(* Logix 5000 project; controller PDPMV1_60_v15 vendor 1 type 14 code 65 rev 15.1; software revision 15.00 *)
// MVI69-PDPMV1 sample ladder logic.

TASK MainTask (continuous, watchdog 500 ms) : MainProgram

MODULES
   Controller : vendor 1 type 14 code 65 (CompactLogixL35Controller 0, rev 15.1)
      LocalENB : 1769-L35E Ethernet Port (CompactLogixL35Ethernet 1, rev 15.1)
      Local : CompactBus (CompactVirtualAdapter 3, rev 15.1, Output RPI 2 ms)
         PDPMV1_60 : 1769-MODULE (Compact 1, rev 1.1, Output RPI 2 ms)   // MVI69-PDPMV1
END_MODULES

TYPE PDPMV1_AbortConnection :
STRUCT
   Out : PDPMV1_AbortConnection_out;   // Mailbox Request
   In : PDPMV1_AbortConnection_In;   // Mailbox Response
END_STRUCT
END_TYPE

TYPE PDPMV1_AbortConnection_In :
STRUCT
   C_REF : INT;   // Connection reference that shall be terminated.
   ReasonCode : SINT;   // Indicates the reason for the abort request. Value is user-specific. Range 0...15
   Subnet : SINT;   // This parameter encodes information about the origin of the abort initiator. 0: No 1: Local 2: Remote 3...255: (reserved)
   ExtendedFaultInformation : INT;   // If ‘Fault Information’ equals 000Ah or 000Bh, additional information of the error can be found
   FaultInformation : INT;   // If ‘Invalid Other’ is returned in the Message Information word in the header of the response,
END_STRUCT
END_TYPE

TYPE PDPMV1_AbortConnection_out :
STRUCT
   C_REF : INT;   // Connection reference that shall be terminated
   ReasonCode : SINT;   // Indicates the reason for the abort request. Value is user-specific. Range 0...15.
   Subnet : SINT;   // This parameter encodes information about the origin of the abort initiator. 0: No 1: Local 2: Remote
END_STRUCT
END_TYPE

TYPE PDPMV1_Alarm :   // DPV1 alarm data received by the module
STRUCT
   ByteCount : INT;   // Byte count data block
   SlotNumber : SINT;   // Used in the slave to address the desired data block. Range 0-254
   SlaveAddress : SINT;   // Destination of slave (1-125)
   AlarmSpecAck : SINT;   // Additional alarm information
   SeqNumber : SINT;   // Unique ID number of the alarm. Range 0-31.
   ExtDiag : SINT;   // Extended Diagnostic Flag (FFh - flag set and 00h - flag cleared).
   AlarmType : SINT;   // Identifies alarm type. Range is from 1 to 6, 32 to 126.
   FaultInformation : SINT;   // If other than 0, refer to user manual for code information
   Data : SINT[500];   // Returned data [1...n] array with additional manf. spec alarm info.
END_STRUCT
END_TYPE

TYPE PDPMV1_backplane :   // This object stores variables used by the sample ladder for handshaking.
STRUCT
   Read : INT;   // Backplane read statistics
   Write : INT;   // Backplane write statistics
   Error : INT;   // Backplane error statistics
   LastRead : INT;   // Last read block index received from the module
   LastWrite : INT;   // Last write block index received from the module
   BlockIndex : INT;   // Block index of each copy of PROFIBUS input and output blocks
END_STRUCT
END_TYPE

TYPE PDPMV1_backplane2 :   // This object stores variables used by the sample ladder for handshaking.
STRUCT
   LastRead : INT;   // Last read block index received from the module
   LastWrite : INT;   // Last write block index received from the module
   BlockIndex : INT;   // Block index of each copy of PROFIBUS input and output blocks
END_STRUCT
END_TYPE

TYPE PDPMV1_Class1AcyclicRead :   // DPV1 acyclic read mailbox data structure
STRUCT
   Out : PDPMV1_Class1AcyclicRead_Out;   // Mailbox request
   In : PDPMV1_Class1AcyclicRead_In;   // Mailbox response
END_STRUCT
END_TYPE

TYPE PDPMV1_Class1AcyclicRead_In :   // DPV1 acyclic read mailbox response
STRUCT
   ByteCount : INT;   // Byte count data block
   SlotNumber : SINT;   // Used in the slave to address the desired data block.
   SlaveAddress : SINT;   // Destination of slave (1-125)
   Length : SINT;   // Specifies the number of bytes of the data block to read
   Index : SINT;   // Index block
   ErrorDecode : SINT;   // If other than 0, refer to user manual for code information
   ErrorCode2 : SINT;   // If other than 0, refer to user manual for code information
   ErrorCode1 : SINT;   // If other than 0, refer to user manual for code information
   ExtendedFaultInfo : SINT;   // If other than 0, refer to user manual for code information
   FaultInformation : SINT;   // If other than 0, refer to user manual for code information
   Data : SINT[300];   // Returned data [1...n] array
END_STRUCT
END_TYPE

TYPE PDPMV1_Class1AcyclicRead_Out :   // DPV1 acyclic read mailbox request
STRUCT
   SlotNumber : SINT;   // Used in the slave to address the desired data block.
   SlaveAddress : SINT;   // Destination of slave (1-125)
   DataSize : INT;   // Object data size
   Length : SINT;   // Specifies the number of bytes of the data block to read
   Index : SINT;   // Index block
END_STRUCT
END_TYPE

TYPE PDPMV1_Class1AcyclicWrite :   // DPV1 acyclic write mailbox data structure
STRUCT
   Out : PDPMV1_Class1AcyclicWrite_Out;   // Mailbox request
   In : PDPMV1_Class1AcyclicWrite_In;   // Mailbox response
END_STRUCT
END_TYPE

TYPE PDPMV1_Class1AcyclicWrite_In :   // DPV1 acyclic write mailbox response
STRUCT
   ByteCount : INT;   // Byte count data block
   SlotNumber : SINT;   // Used in the slave to address the desired data block.
   SlaveAddress : SINT;   // Destination of slave (1-125)
   Length : SINT;   // Specifies the number of bytes of the data block to read
   Index : SINT;   // Index block
   ErrorDecode : SINT;   // If other than 0, refer to user manual for code information
   ErrorCode2 : SINT;   // If other than 0, refer to user manual for code information
   ErrorCode1 : SINT;   // If other than 0, refer to user manual for code information
   ExtendedFaultInfo : SINT;   // If other than 0, refer to user manual for code information
   FaultInformation : SINT;   // If other than 0, refer to user manual for code information
   Data : SINT[300];   // Returned data [1...n] array
END_STRUCT
END_TYPE

TYPE PDPMV1_Class1AcyclicWrite_Out :   // DPV1 acyclic write mailbox request
STRUCT
   SlotNumber : SINT;   // Used in the slave to address the desired data block.
   SlaveAddress : SINT;   // Destination of slave (1-125)
   DataSize : INT;   // Object data size
   Length : SINT;   // Specifies the number of bytes of the data block to read
   Index : SINT;   // Index Block
   Data : SINT[300];   // Data that should be written [1...n]
END_STRUCT
END_TYPE

TYPE PDPMV1_Class2AcyclicRead :
STRUCT
   Out : PDPMV1_Class2AcyclicRead_Out;   // Mailbox request
   In : PDPMV1_Class2AcyclicRead_In;   // Mailbox response
END_STRUCT
END_TYPE

TYPE PDPMV1_Class2AcyclicRead_In :
STRUCT
   DataSize : INT;   // Byte count data block
   C_REF : INT;   // Connections references used to identify the connection later on. Range: 1-128
   Index : SINT;   // Index block
   SlotNumber : SINT;   // Used in the slave to address the desired data block.
   Length : INT;   // Specifies the number of bytes of the data block to read
   ErrorDecode : INT;   // If other than 0, refer to user manual for code information
   ErrorCode2 : SINT;   // If other than 0, refer to user manual for code information
   ErrorCode1 : SINT;   // If other than 0, refer to user manual for code information
   ExtendedFaultInfo : SINT;   // If other than 0, refer to user manual for code information
   FaultInformation : SINT;   // If other than 0, refer to user manual for code information
   Data : SINT[244];   // Returned data [1...n] array
END_STRUCT
END_TYPE

TYPE PDPMV1_Class2AcyclicRead_Out :
STRUCT
   C_REF : INT;   // Connection reference that shall be terminated
   Index : SINT;   // Used in the slave for addressing of the desired data block. Range 0...254
   SlotNumber : SINT;   // Used in the slave for addressing of the desired data block. Range 0...254
   Length : INT;   // Number of bytes to write
END_STRUCT
END_TYPE

TYPE PDPMV1_Class2AcyclicWrite :   // DPV1 acyclic write mailbox data structure
STRUCT
   Out : PDPMV1_Class2AcyclicWrite_Out;   // Mailbox request
   In : PDPMV1_Class2AcyclicWrite_In;   // Mailbox response
END_STRUCT
END_TYPE

TYPE PDPMV1_Class2AcyclicWrite_In :   // DPV1 acyclic write mailbox response
STRUCT
   ByteCount : INT;   // Byte count data block
   C_REF : INT;   // Connection reference that shall be Read
   Index : SINT;   // Index block
   SlotNumber : SINT;   // Used in the slave to address the desired data block.
   Length : SINT;   // Specifies the number of bytes of the data block to read
   ErrorDecode : SINT;   // If other than 0, refer to user manual for code information
   ErrorCode2 : SINT;   // If other than 0, refer to user manual for code information
   ErrorCode1 : SINT;   // If other than 0, refer to user manual for code information
   ExtendedFaultInfo : SINT;   // If other than 0, refer to user manual for code information
   FaultInformation : SINT;   // If other than 0, refer to user manual for code information
   Data : SINT[244];   // Returned data [1...n] array
END_STRUCT
END_TYPE

TYPE PDPMV1_Class2AcyclicWrite_Out :   // DPV1 acyclic write mailbox request
STRUCT
   DataSize : INT;   // Object data size
   C_REF : INT;   // Connection reference that shall be terminated
   Index : SINT;   // Index block
   SlotNumber : SINT;   // Used in the slave to address the desired data block.
   Length : INT;   // Specifies the number of bytes of the data block to read
   Data : SINT[244];   // Data that should be written [1...n]
END_STRUCT
END_TYPE

TYPE PDPMV1_Command :   // This object contains the command bits that request mailbox messages from the module.
STRUCT
   StopMode : BOOL;   // Set the module to stop mode (PROFIBUS communication is interrupted in stop mode)
   OperateMode : BOOL;   // Set the module to operate mode (module only communicates through PROFIBUS)
   ClearMode : BOOL;   // Set the module to clear mode (outputs are disabled)
   SynchCRC : BOOL;   // CRC synchronization
   GetLiveList : BOOL;   // Request the Live List information from the module
   GetSlaveConfig : BOOL;   // Request configuration information from slave
   SetSlaveMode : BOOL;   // Set the module to stop mode (PROFIBUS communication is interrupted in stop mode)
   GetSlaveDiagnostics : BOOL;   // Requests slave diagnostics from a slave
   SetSlaveAddress : BOOL;   // Change the slave's PROFIBUS address 100 (only if slave supports this feature)
   StartSlaves : BOOL;   // Restarts PROFIBUS communication with one or more slaves after a "StopSlave" mailbox
   StopSlaves : BOOL;   // Stop PROFIBUS communication with one or more slaves
   Class1AcyclicRead : BOOL;   // Request the module to send acyclic read message to slave
   Class1AcyclicWrite : BOOL;   // Request the module to send acyclic write message to the slave
   InitiateConnection : BOOL;   // Request to establish connection with a V1 slave that can handle class 2 messages
   AbortConnection : BOOL;   // Request to Abort an already established connection with a V1 slave that can handle class 2 messages
   Class2AcyclicRead : BOOL;   // Request the module to send class 2 acyclic Read message to a V1 slave
   Class2AcyclicWrite : BOOL;   // Request the module to send class 2 acyclic Write message to a V1 slave
END_STRUCT
END_TYPE

TYPE PDPMV1_Control :   // Control status
STRUCT
   serial_number : SINT[4];   // Module serial number
   version_MSB : SINT;   // Module version number (most significant byte)
   version_LSB : SINT;   // Module version number (least significant byte)
   mod_status_MSB : SINT;   // Module status (most significant byte)
   mod_status_LSB : SINT;   // Module status (least significant byte)
END_STRUCT
END_TYPE

TYPE PDPMV1_ControlCommand :   // Option bits for SetSlaveMode mailbox
STRUCT
   Reserved1 : BOOL;   // Reserved
   Reserved2 : BOOL;   // Reserved
   Unfreeze_Input : BOOL;   // Freeze mode is concluded when initiated
   Freeze_Input : BOOL;   // Causes the addressed slave to assume freeze mode.
   Unsynchronize_Output : BOOL;   // Unsynchronized output data
   Synchronize_Output : BOOL;   // Synchronized output data
   Reserved3 : BOOL[32];   // Reserved
END_STRUCT
END_TYPE

TYPE PDPMV1_CRC :   // This object stores CRC values for both Profibus and the module.
STRUCT
   ProfibusCRC : DINT;   // Stores Profibus CRC32 values
   ModuleCRC : DINT;   // Stores Module CRC32 values
END_STRUCT
END_TYPE

TYPE PDPMV1_CRC_Struct :   // Module CRC structures
STRUCT
   In : PDPMV1_CRC;   // Mailbox response
   Out : PDPMV1_CRC;   // Mailbox request
END_STRUCT
END_TYPE

TYPE PDPMV1_Fieldbus :   // Fieldbus status
STRUCT
   FB_Slave_Cfg_List : SINT[16];   // Bitmap structure containing PROFIBUS slave configuration (bit x = 1 means slave x is configured)
   FB_Slave_Data_xfer : SINT[16];   // Bitmap structure containing PROFIBUS slave data exchange status (bit x = 1 means slave x is transferring data to the module)
   FB_Slave_Diag : SINT[16];   // Bitmap structure containing PROFIBUS slave diagnostic info (bit x = 1 means slave x is reporting diagnostics)
   FB_Pad_Byte : SINT;   // Reserved
   FB_op_state : SINT;   // Operation state ( 00 = offline, 40 = stop, 80 = clear, C0= operate)
   FB_ident_MSB : SINT;   // Master identification code (most significant byte)
   FB_ident_LSB : SINT;   // Master identification code (least significant byte)
END_STRUCT
END_TYPE

TYPE PDPMV1_GetLiveList :   // GetLiveList mailbox to retrieve the live list information from PROFIBUS network, informing the slaves that are communicating
STRUCT
   ReturnCode : SINT;   // Returned code about the nodes on the network
   FaultInfo : SINT;   // If other than 0, refer to user manual for code information
   Station : SINT[127];   // Station type contents.
END_STRUCT
END_TYPE

TYPE PDPMV1_GetSlaveConfig :   // GetSlaveConfig mailobox to retrieve configuration data from specific PROFIBUS slaves
STRUCT
   Out : PDPMV1_GetSlaveConfig_Out;   // mailbox request
   In : PDPMV1_GetSlaveConfig_In;   // mailbox response
END_STRUCT
END_TYPE

TYPE PDPMV1_GetSlaveConfig_In :   // GetSlaveConfig mailbox response
STRUCT
   ByteCount : INT;   // Byte count data block
   WordCount : INT;   // Word count data block
   SlaveAddress : INT;   // Destination of slave (1-125)
   ErrorCode : INT[1];   // If other than 0, refer to user manual for code information
   ReturnCode : INT;   // If other than 0, refer to user manual for code information
   FaultInformation : INT;   // If other than 0, refer to user manual for code information
   Identifier : SINT[245];   // Configuration from a specific connected PROFIBUS slave
END_STRUCT
END_TYPE

TYPE PDPMV1_GetSlaveConfig_Out :   // GetSlaveConfig mailbox request
STRUCT
   SlaveAddress : INT;   // Destination of slave (1-125)
END_STRUCT
END_TYPE

TYPE PDPMV1_GetSlaveDiagnostics :   // GetSlaveDiagnostics mailbox to retrieve diagnostic information from specific PROFIBUS slaves
STRUCT
   Out : PDPMV1_GetSlaveDiagnostics_Out;   // Mailbox request
   In : PDPMV1_GetSlaveDiagnostics_In;   // Mailbox response
END_STRUCT
END_TYPE

TYPE PDPMV1_GetSlaveDiagnostics_In :   // GetSlaveDiagnostics mailbox response
STRUCT
   RequestType : SINT;   // Type of request. 0 to use module memory RAM or 1 for live PROFIBUS network.
   SlaveAddress : SINT;   // Destination of slave (Range 1-125)
   ExtendedFaultInfo : INT;   // If other than 0, refer to user manual for code information
   FaultInformation : INT;   // If other than 0, refer to user manual for code information
   StationStatus1_2 : INT;   // Status of station types 1 and 2
   StationStatus3_4 : INT;   // Status of station types 3 and 4
   IdentNumber : INT;   // Unique ID assigned by the PROFIBUS User Organization
   ExtendedDiagnosticData : INT[200];   // Slave user-specific data. Refer to actual slave documentation for info
END_STRUCT
END_TYPE

TYPE PDPMV1_GetSlaveDiagnostics_Out :   // GetSlaveDiagnostics mailbox request
STRUCT
   RequestType : SINT;   // Type of request. 0 to use module memory RAM or 1 for live PROFIBUS network.
   SlaveAddress : SINT;   // Destination of slave (Range 1-125)
END_STRUCT
END_TYPE

TYPE PDPMV1_InitiateConnection :
STRUCT
   Out : PDPMV1_InitiateConnection_out;   // Mailbox Request
   In : PDPMV1_InitiateConnection_In;   // Mailbox response
END_STRUCT
END_TYPE

TYPE PDPMV1_InitiateConnection_In :   // This tag holds the response parameters after the user sends mailbox to initiate connection with V1 slave
STRUCT
   SizeofdatainBytes : INT;   // Size of data being read
   C_REF : INT;   // Connections references used to identify the connection later on. Range: 1-128
   MaxDataLength : SINT;   // The slave’s maximum data length in bytes (reported by the slave in DP Initiate.res).
   SlaveAddress : SINT;   // Address of the slave to which a connection shall be established. Range: 0...126
   MinmumSlaveTimeout : INT;   // The minimum slave timeout value supported by the slave (in multiples of 10ms).
   ErrorDecode : SINT;   // If ‘Fault Information’ equals 0010h, additional information according to the DPV1 specification
   ErrorCode2 : SINT;   // If ‘Fault Information’ equals 0010h, additional information according to the DPV1 specification
   ErrorCode1 : SINT;   // If ‘Fault Information’ equals 0010h, additional information according to the DPV1 specification
   ExtendedFaultInformation : INT;   // If ‘Fault Information’ equals 000Ah or 000Bh, additional information of the error can be found
   FaultInformation : INT;   // If ‘Invalid Other’ is returned in the Message Information word in the header of the response,
   SendTimeout : INT;   // Defines the control time (timebase 10ms) for the supervision of the connection between the slave and the master. Range 6...655
   FeatureSupported2 : SINT;   // (reserved for future use)
   FeatureSupported1 : SINT;   // Identifies the supported C2-service functionality as follows: b0: DPV1_RW. This bit is set if the services C2_Read and C2_Write
   ProfileFeatures2 : SINT;   // Identifies the supported service functionality regarding the used profile definition. The meaning of these registers are profil
   ProfileFeatures1 : SINT;   // Identifies the supported service functionality regarding the used profile definition. The meaning of these registers are profil
   ProfileIdentNumber : INT;   // This parameter identifies a unique profile definition. The Profile Ident Number is taken from the pool of Ident Numbers managed
   S_Length : SINT;   // This parameter specifies the length of the S_Address parameter (see table below). Default value is 02h.
   S_Type : SINT;   // This parameter indicates the presence of the optional Network/MAC address of the source. b0: 1: A Network/MAC address is presen
   D_Length : SINT;   // This value specifies the length of the D_Address parameter (see table below). Default value is 02h.
   D_Type : SINT;   // This parameter indicates the presence of the optional Network/MAC address of the destination. b0: 1: A Network/MAC address is p
   S_Address : INT;   // This field holds additional address information about the source.
   D_Address : INT;   // This field holds additional address information about the destination.
END_STRUCT
END_TYPE

TYPE PDPMV1_InitiateConnection_out :
STRUCT
   SlaveAddress : INT;   // Address of the slave to which a connection shall be established. Range: 0...126
   C_REF : INT;   // Connections references used to identify the connection later on. Range: 1-128
END_STRUCT
END_TYPE

TYPE PDPMV1_Mailbox :   // Stores all mailbox request and response registers
STRUCT
   GetLiveList : PDPMV1_GetLiveList;   // Gets information from all nodes on the network
   GetSlaveConfig : PDPMV1_GetSlaveConfig;   // Get slave configuration
   SetSlaveMode : PDPMV1_SetSlaveMode;   // Send special control command to one or several slaves (Sync/Freeze)
   GetSlaveDiagnostics : PDPMV1_GetSlaveDiagnostics;   // Get diagnostic information from a slave
   SetSlaveAddress : PDPMV1_SetSlaveAddress;   // Set node address of a slave (if supported by the slave)
   StartStopSlaves : PDPMV1_Start_Stop_Slaves;   // Start/Stop slaves dynamically
   Class1AcyclicRead : PDPMV1_Class1AcyclicRead;   // Initiates a DPV1 class 1 acyclic read request.
   Class1AcyclicWrite : PDPMV1_Class1AcyclicWrite;   // Initiates a DPV1 class 1 acyclic write request.
   Alarm : PDPMV1_Alarm;   // Alarm message transferred by a slave to the master
   InitiateConnection : PDPMV1_InitiateConnection;   // mailbox form used to initiate connection with v1 slave before sending class2 messages.
   AbortConnection : PDPMV1_AbortConnection;   // mailbox form used to abort an already established connection with v1 slave before sending class2 messages.
   Class2AcyclicRead : PDPMV1_Class2AcyclicRead;   // mailbox form used to send a class 2 messages to read acyclic data
   Class2AcyclicWrite : PDPMV1_Class2AcyclicWrite;   // mailbox form used to send a class 2 messages to write acyclic data
END_STRUCT
END_TYPE

TYPE PDPMV1_MBControl :   // PDPMV1 Mailbox Control status.
STRUCT
   Out_MB_index : INT;   // Reserved
   In_MB_index : INT;   // Reserved
   Alarm_MB_index : INT;   // Reserved
   In_Last_Out_MB : INT;   // Last out MB message ID
   In_Last_In_MB : INT;   // Current in mailbox
   In_Last_Alarm_MB : INT;   // Current alarm control
   Out_Last_Out_MB : INT;   // Reserved
   Out_Last_In_MB : INT;   // Reserved
   Out_Last_Alarm_MB : INT;   // Reserved
END_STRUCT
END_TYPE

TYPE PDPMV1_Module :   // Status data
STRUCT
   Mod_scan_count : INT;   // Incremented every module scan loop
   Mod_output_update : INT;   // Incremented at every output scan
   Mod_input_update : INT;   // Incremented at every input scan
   Mod_out_MB : INT;   // Incremented at every output mailbox processing
   Mod_in_MB : INT;   // Incremented at every intput mailbox processing
   Mod_alarm_ind : INT;   // Incremented at every alarm indication
   Mod_alarm_con : INT;   // Incremented at every alarm confirmation
   Reserved1 : INT;   // Reserved
   Reserved2 : INT;   // Reserved
END_STRUCT
END_TYPE

TYPE PDPMV1_Module_Data :   // Module data for mailbox messaging
STRUCT
   Variables : PDPMV1_MBControl;   // PDPMV1 Mailbox Control status.
END_STRUCT
END_TYPE

TYPE PDPMV1_ModuleDef :   // Main module definition
STRUCT
   Output : SINT[1536];   // Output data
   Input : SINT[1536];   // Input data
   BP : PDPMV1_backplane2;   // Backplane status
   Status : PDPMV1_Status;   // Module status information
   MailboxCommand : PDPMV1_Command;   // Mailbox Command
   Mailbox : PDPMV1_Mailbox;   // Mailbox tags for optional applications
   CRC : PDPMV1_CRC_Struct;   // CRC status
   MailboxControl : PDPMV1_MBControl;   // Mailbox Control
   Util : PDPMV1_Util;   // Internal tags used for ladder logic processing. User applications should not overwrite any Util tags
END_STRUCT
END_TYPE

TYPE PDPMV1_other_status :   // This object contains specific information, such as the number of mailbox and alarms located in the mailbox queue.
STRUCT
   Cfg_file_error : INT;   // Bit0 = PDPMV1.CFG, Bit 1 = WATTCP.CFG, Bit 2 = PDPMV1.DDB, Bit3=PDPMV1.XML
   R_120 : INT;   // Not Used
   R_122 : INT;   // Not Used
   R_124 : INT;   // Not Used
   R_126 : INT;   // Not Used
   R_128 : INT;   // Not Used
   R_130 : INT;   // Not Used
   R_132 : INT;   // Not Used
   R_134 : INT;   // Not Used
   R_136 : INT;   // Not Used
   R_138 : INT;   // Not Used
   R_140 : INT;   // Not Used
   R_142 : INT;   // Not Used
   R_144 : INT;   // Not Used
   In_MB_queue : INT;   // Number of messages in the input mailbox queue
   Out_MB_queue : INT;   // Number of messages in the output mailbox queue
   Alarm_MB_queue : INT;   // Number of messages in the alarm mailbox queue
   Last_out_MB : INT;   // Number of messages in the output mailbox queue
   Cur_in_MB : INT;   // Number of messages currently in the input mailbox queue
   Cur_alarm_MB : INT;   // Number of messages currently in the alarm mailbox queue
END_STRUCT
END_TYPE

TYPE PDPMV1_SetSlaveAddress :   // SetSlaveAddress mailbox that allows the module to dynamically change a PRIDUBUS address (only for slaves that supports it)
STRUCT
   Out : PDPMV1_SetSlaveAddress_Out;   // Mailbox request
   In : PDPMV1_SetSlaveAddress_In;   // Mailbox response
END_STRUCT
END_TYPE

TYPE PDPMV1_SetSlaveAddress_In :   // Mailbox response
STRUCT
   ByteCount : INT;   // Byte count data block
   NewSlaveAddress : SINT;   // Range 1 to 125, specifies the new address of the slave
   CurrentSlaveAddress : SINT;   // Range 1 to 125, specifies the current address of the slave
   SlaveIdentNumber : INT;   // Indent number for the slave
   No_add_Chg : INT;   // Specifies whether it is allowed to change the slave address again later
   ErrorCode1_2 : INT;   // If other than 0, refer to user manual for code information
   ErrorCode3_4 : INT;   // If other than 0, refer to user manual for code information
   ReturnCode : INT;   // If other than 0, refer to user manual for code information
   FaultInformation : INT;   // If other than 0, refer to user manual for code information
   MessageDataByte : SINT[400];   // Message data byte array for user-specific data
END_STRUCT
END_TYPE

TYPE PDPMV1_SetSlaveAddress_Out :   // Mailbox request
STRUCT
   ByteCount : INT;   // Byte count data block
   NewSlaveAddress : SINT;   // Range 1 to 125, specifies the new address of the slave
   CurrentSlaveAddress : SINT;   // Range 1 to 125, specifies the current address of the slave
   SlaveIdentNumber : INT;   // Indent number for the slave
   No_add_Chg : INT;   // specifies whether it is allowed to change the slave address again later
   MessageDataByte : SINT[400];   // Message data byte array for user-specific data
END_STRUCT
END_TYPE

TYPE PDPMV1_SetSlaveMode :   // SetSlaveMode mailbox that allows the processor to change the slave mode to interrupt input or output data update
STRUCT
   Out : PDPMV1_SetSlaveMode_Out;   // Mailbox Request
   In : PDPMV1_SetSlaveMode_In;   // Mailbox Response
END_STRUCT
END_TYPE

TYPE PDPMV1_SetSlaveMode_In :   // Mailbox response
STRUCT
   GroupSelect : SINT;   // Range 01h to FFh (Bit Coded). This parameter determines which group to address. Refer to the user manual for examples
   SlaveAddress : SINT;   // Range 1 to 125; 127 (Multicast address).
   ControlCommand : PDPMV1_ControlCommand;   // This parameter specifies the command to send (Unsync/Sync and Unfreeze/Freeze).
   ExtendedFaultInfo : INT;   // If other than 0, refer to user manual for code information
   FaultInformation : INT;   // If other than 0, refer to user manual for code information
END_STRUCT
END_TYPE

TYPE PDPMV1_SetSlaveMode_Out :   // Mailbox Request
STRUCT
   GroupSelect : SINT;   // Range 01h to FFh (Bit Coded). This parameter determines which group to address. Refer to the user manual for examples
   SlaveAddress : SINT;   // Range 1 to 125; 127 (Multicast address).
   ControlCommand : PDPMV1_ControlCommand;   // This parameter specifies the command to send (Unsync/Sync and Unfreeze/Freeze).
END_STRUCT
END_TYPE

TYPE PDPMV1_Start_Stop_Slaves :   // Start/Stop Slaves mailbox allows the processor to restart or hault slave communication.
STRUCT
   Out : PDPMV1_Start_Stop_Slaves_Out;   // Mailbox Request
   In : PDPMV1_Start_Stop_Slaves_In;   // Mailbox Response
END_STRUCT
END_TYPE

TYPE PDPMV1_Start_Stop_Slaves_In :   // Mailbox response
STRUCT
   AdditionalFaultInfo : INT;   // If other than 0, refer to user manual for code information
   FaultInformation : INT;   // If other than 0, refer to user manual for code information
   SlaveNumber : SINT[126];   // Slave number designation (1-125)
END_STRUCT
END_TYPE

TYPE PDPMV1_Start_Stop_Slaves_Out :   // Mailbox request
STRUCT
   SlaveNumber : SINT[126];   // Slave number designation (1-125)
END_STRUCT
END_TYPE

TYPE PDPMV1_Status :   // Status block 0 or -1 for the MVI56-PDPMV1 module
STRUCT
   Pattern : SINT[12];   // Module indentification code
   Input_Size : INT;   // Input data size
   Output_Size : INT;   // Output data size
   Reserved_16 : INT;   // Reserved
   Reserved_18 : INT;   // Reserved
   Reserved_20 : INT;   // Reserved
   Input_Swap : SINT;   // User configured flag to indicate if input data is swapped before placing in the input image of the controller
   Output_Swap : SINT;   // User configured flag to indicate if output data is swapped before placing in the output image of the controller
   Module_Major_Ver : SINT;   // Module software major version number
   Module_Minor_Ver : SINT;   // Module software minor version number
   Fieldbus : PDPMV1_Fieldbus;   // PROFIBUS network status information
   Control : PDPMV1_Control;   // Module information
   Profibus_CRC32 : DINT;   // Profibus CRC32 value
   Module_CRC32 : DINT;   // Module CRC32 value
   Module : PDPMV1_Module;   // General module status to monitor data, mailbox and alarm exchange between the processor and the module
   Backplane : PDPMV1_backplane;   // Backplane status information
   Other : PDPMV1_other_status;   // General mailbox and cfg error information
END_STRUCT
END_TYPE

TYPE PDPMV1_Util :
STRUCT
   ByteSwapUtil : INT;   // Used for byte swap logic
   TempInt : INT;   // Used for integer formatting
   UtilCount : INT;   // Used for util count range
   Finishmailboxreading : BOOL;   // Used to finish mailbox requests and response reading
   Tempint2 : INT;   // used to copy a value then used for comparison.
   SetSlaveAddress101 : BOOL;   // Change the slave's PROFIBUS address 101 (only if slave supports this feature)
   SetSlaveAddress102 : BOOL;   // Change the slave's PROFIBUS address 102 (only if slave supports this feature)
   Class1AcyclicWrite101 : BOOL;   // Request the module to send acyclic write message to the slave
   Class1AcyclicWrite102 : BOOL;   // Request the module to send acyclic write message to the slave
   Class2AcyclicWrite101 : BOOL;   // Request the module to send Class2 acyclic write message to slave 101
   Class2AcyclicWrite102 : BOOL;   // Request the module to send Class2 acyclic write message to slave 102
   Finishgetlivelist : BOOL;   // Finish requesting the Live List information from the module
   FinishgetSlaveconfig : BOOL;   // Finish requesting configuration information from a slave
   FinishgetSlaveDiagnost : BOOL;   // Finish requesting slave diagnostics from a slave
   FinishSetSlaveAddr : BOOL;   // Finish changing the slaves PROFIBUS addressing
   FinishClass1AcyclicRead : BOOL;   // Finish requesting the module to send acyclic read message to slave
   FinishClass1AcyclicWrite : BOOL;   // Finish requesting the module to send acyclic write message to slave
   FinishStartStopSlaves : BOOL;   // Finish PROFIBUS communications with one or more slaves if supported
   FinishClass2AcyclicRead : BOOL;   // Finish requesting the module to send Class 2 acyclic read message to slave
   FinishClass2AcyclicWrite : BOOL;   // Finish requesting the module to send acyclic write message to slave
END_STRUCT
END_TYPE

VAR_GLOBAL   (* controller tags *)
   MVI69PDPMV1 : PDPMV1_ModuleDef;
END_VAR

PROGRAM MainProgram   (* main routine MainRoutine *)

ROUTINE BuildMailbox   (* ladder *)
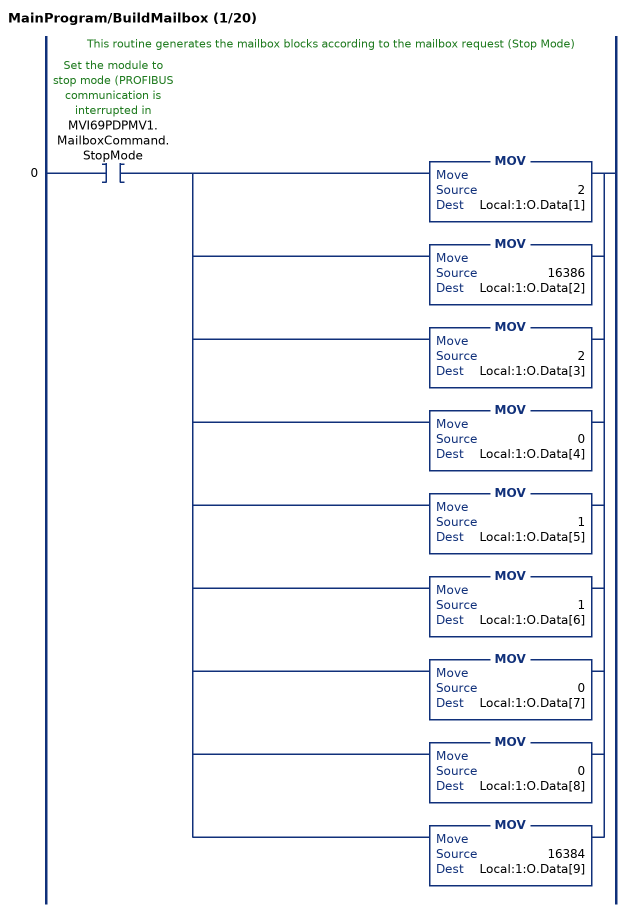
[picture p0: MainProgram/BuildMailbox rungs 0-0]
   // This routine generates the mailbox blocks according to the mailbox request (Stop Mode)
   0: XIC(MVI69PDPMV1.MailboxCommand.StopMode)[MOV(2,Local:1:O.Data[1]) ,MOV(16386,Local:1:O.Data[2]) ,MOV(2,Local:1:O.Data[3]) ,MOV(0,Local:1:O.Data[4]) ,MOV(1,Local:1:O.Data[5]) ,MOV(1,Local:1:O.Data[6]) ,MOV(0,Local:1:O.Data[7]) ,MOV(0,Local:1:O.Data[8]) ,MOV(16384,Local:1:O.Data[9]) ];
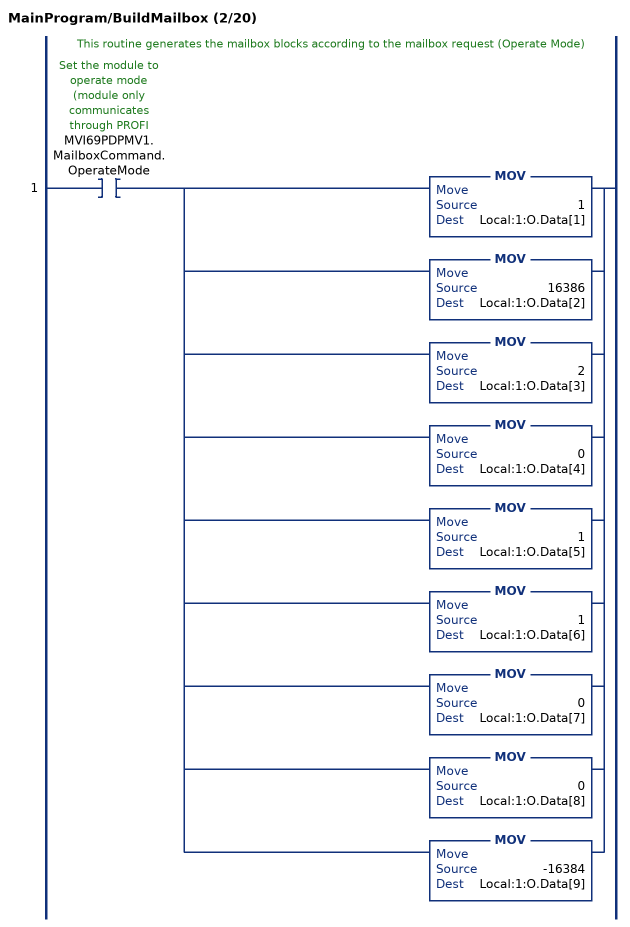
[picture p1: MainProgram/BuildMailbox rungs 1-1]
   // This routine generates the mailbox blocks according to the mailbox request (Operate Mode)
   1: XIC(MVI69PDPMV1.MailboxCommand.OperateMode)[MOV(1,Local:1:O.Data[1]) ,MOV(16386,Local:1:O.Data[2]) ,MOV(2,Local:1:O.Data[3]) ,MOV(0,Local:1:O.Data[4]) ,MOV(1,Local:1:O.Data[5]) ,MOV(1,Local:1:O.Data[6]) ,MOV(0,Local:1:O.Data[7]) ,MOV(0,Local:1:O.Data[8]) ,MOV(-16384,Local:1:O.Data[9]) ];
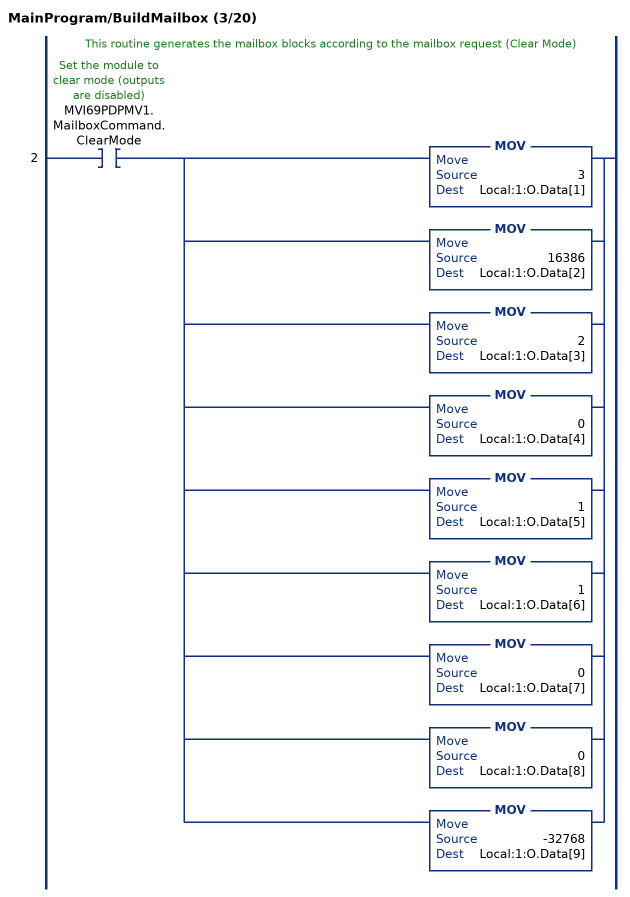
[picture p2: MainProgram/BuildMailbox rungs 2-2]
   // This routine generates the mailbox blocks according to the mailbox request (Clear Mode)
   2: XIC(MVI69PDPMV1.MailboxCommand.ClearMode)[MOV(3,Local:1:O.Data[1]) ,MOV(16386,Local:1:O.Data[2]) ,MOV(2,Local:1:O.Data[3]) ,MOV(0,Local:1:O.Data[4]) ,MOV(1,Local:1:O.Data[5]) ,MOV(1,Local:1:O.Data[6]) ,MOV(0,Local:1:O.Data[7]) ,MOV(0,Local:1:O.Data[8]) ,MOV(-32768,Local:1:O.Data[9]) ];
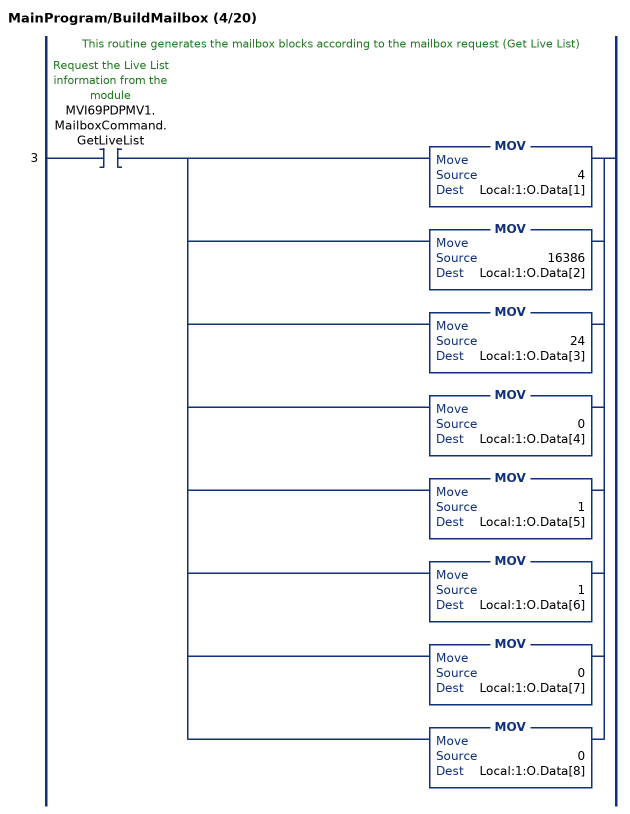
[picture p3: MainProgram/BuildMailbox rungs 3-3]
   // This routine generates the mailbox blocks according to the mailbox request (Get Live List)
   3: XIC(MVI69PDPMV1.MailboxCommand.GetLiveList)[MOV(4,Local:1:O.Data[1]) ,MOV(16386,Local:1:O.Data[2]) ,MOV(24,Local:1:O.Data[3]) ,MOV(0,Local:1:O.Data[4]) ,MOV(1,Local:1:O.Data[5]) ,MOV(1,Local:1:O.Data[6]) ,MOV(0,Local:1:O.Data[7]) ,MOV(0,Local:1:O.Data[8]) ];
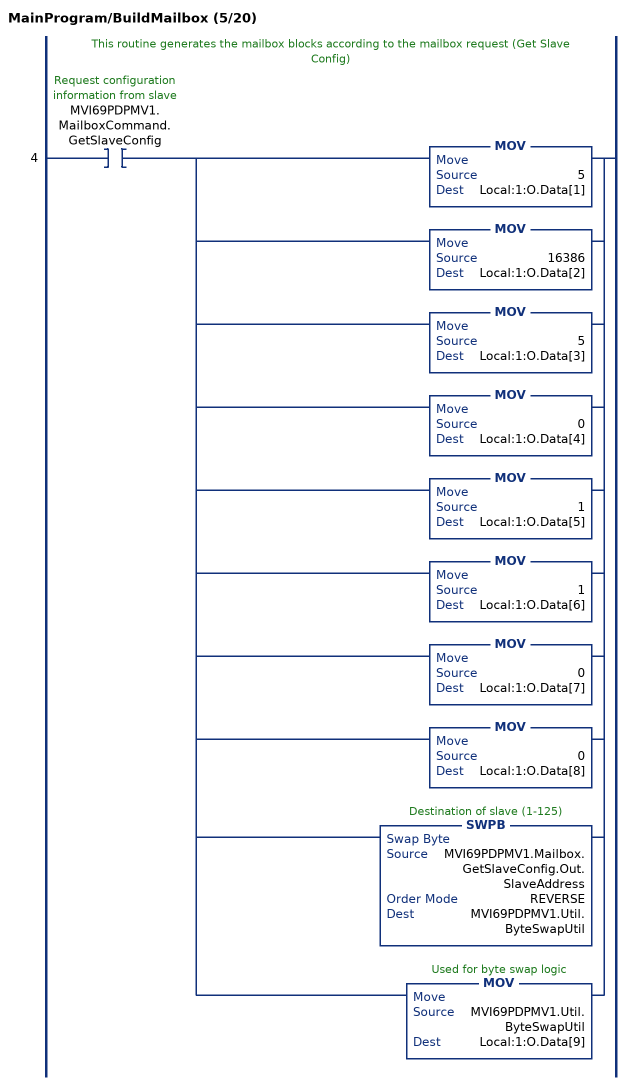
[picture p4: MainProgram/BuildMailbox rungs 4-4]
   // This routine generates the mailbox blocks according to the mailbox request (Get Slave Config)
   4: XIC(MVI69PDPMV1.MailboxCommand.GetSlaveConfig)[MOV(5,Local:1:O.Data[1]) ,MOV(16386,Local:1:O.Data[2]) ,MOV(5,Local:1:O.Data[3]) ,MOV(0,Local:1:O.Data[4]) ,MOV(1,Local:1:O.Data[5]) ,MOV(1,Local:1:O.Data[6]) ,MOV(0,Local:1:O.Data[7]) ,MOV(0,Local:1:O.Data[8]) ,SWPB(MVI69PDPMV1.Mailbox.GetSlaveConfig.Out.SlaveAddress,REVERSE,MVI69PDPMV1.Util.ByteSwapUtil) ,MOV(MVI69PDPMV1.Util.ByteSwapUtil,Local:1:O.Data[9]) ];
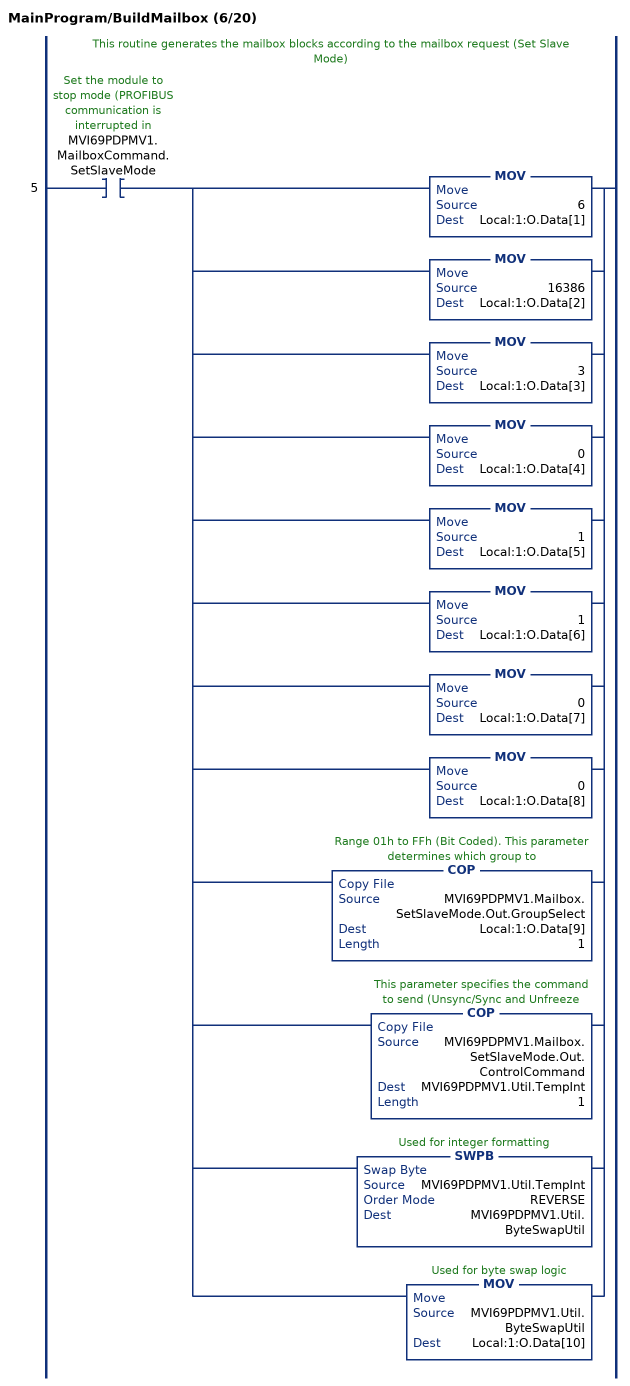
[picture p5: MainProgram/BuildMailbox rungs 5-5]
   // This routine generates the mailbox blocks according to the mailbox request (Set Slave Mode)
   5: XIC(MVI69PDPMV1.MailboxCommand.SetSlaveMode)[MOV(6,Local:1:O.Data[1]) ,MOV(16386,Local:1:O.Data[2]) ,MOV(3,Local:1:O.Data[3]) ,MOV(0,Local:1:O.Data[4]) ,MOV(1,Local:1:O.Data[5]) ,MOV(1,Local:1:O.Data[6]) ,MOV(0,Local:1:O.Data[7]) ,MOV(0,Local:1:O.Data[8]) ,COP(MVI69PDPMV1.Mailbox.SetSlaveMode.Out.GroupSelect,Local:1:O.Data[9],1) ,COP(MVI69PDPMV1.Mailbox.SetSlaveMode.Out.ControlCommand,MVI69PDPMV1.Util.TempInt,1) ,SWPB(MVI69PDPMV1.Util.TempInt,REVERSE,MVI69PDPMV1.Util.ByteSwapUtil) ,MOV(MVI69PDPMV1.Util.ByteSwapUtil,Local:1:O.Data[10]) ];
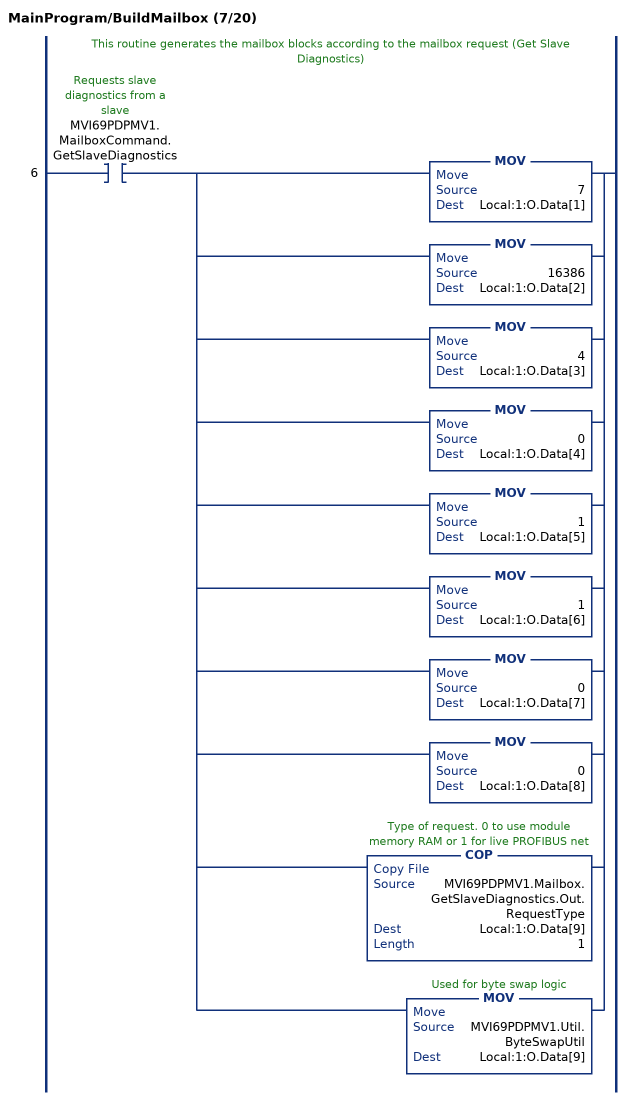
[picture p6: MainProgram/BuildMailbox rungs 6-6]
   // This routine generates the mailbox blocks according to the mailbox request (Get Slave Diagnostics)
   6: XIC(MVI69PDPMV1.MailboxCommand.GetSlaveDiagnostics)[MOV(7,Local:1:O.Data[1]) ,MOV(16386,Local:1:O.Data[2]) ,MOV(4,Local:1:O.Data[3]) ,MOV(0,Local:1:O.Data[4]) ,MOV(1,Local:1:O.Data[5]) ,MOV(1,Local:1:O.Data[6]) ,MOV(0,Local:1:O.Data[7]) ,MOV(0,Local:1:O.Data[8]) ,COP(MVI69PDPMV1.Mailbox.GetSlaveDiagnostics.Out.RequestType,Local:1:O.Data[9],1) ,MOV(MVI69PDPMV1.Util.ByteSwapUtil,Local:1:O.Data[9]) ];
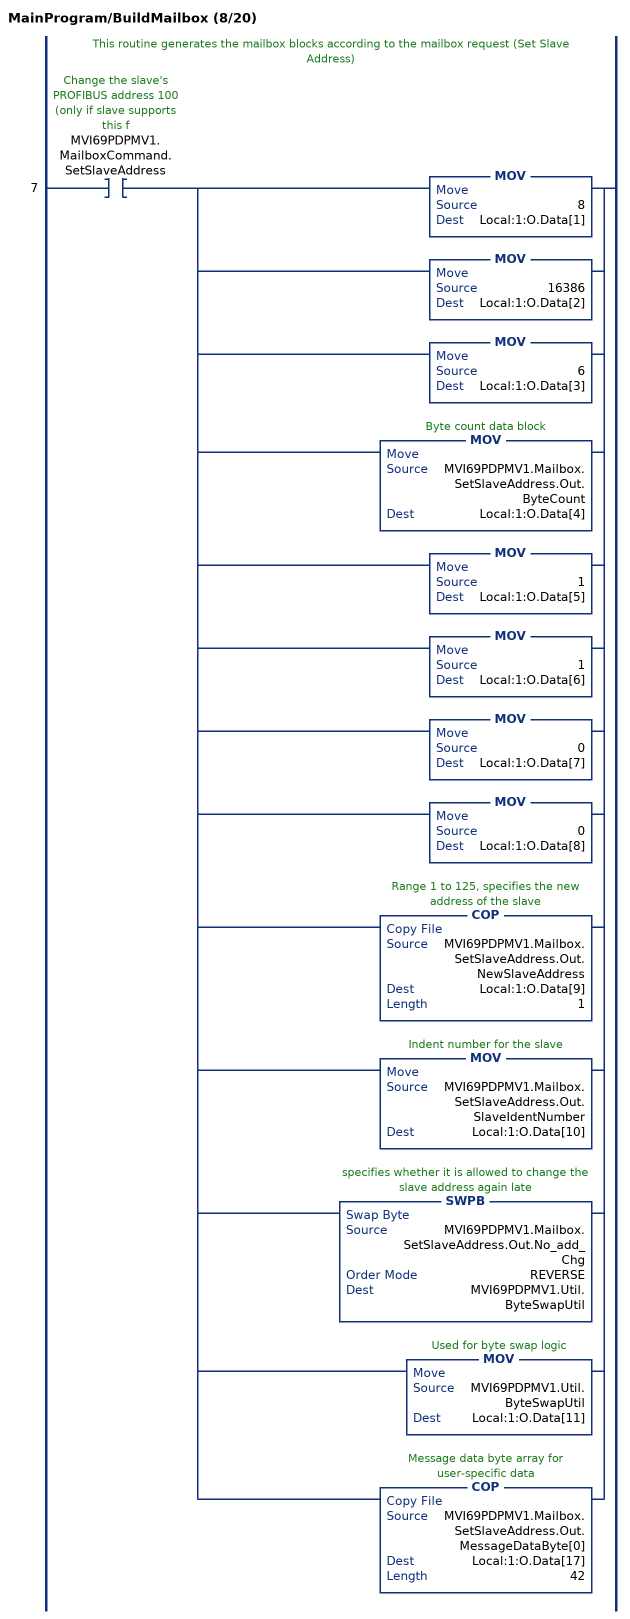
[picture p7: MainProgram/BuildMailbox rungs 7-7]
   // This routine generates the mailbox blocks according to the mailbox request (Set Slave Address)
   7: XIC(MVI69PDPMV1.MailboxCommand.SetSlaveAddress)[MOV(8,Local:1:O.Data[1]) ,MOV(16386,Local:1:O.Data[2]) ,MOV(6,Local:1:O.Data[3]) ,MOV(MVI69PDPMV1.Mailbox.SetSlaveAddress.Out.ByteCount,Local:1:O.Data[4]) ,MOV(1,Local:1:O.Data[5]) ,MOV(1,Local:1:O.Data[6]) ,MOV(0,Local:1:O.Data[7]) ,MOV(0,Local:1:O.Data[8]) ,COP(MVI69PDPMV1.Mailbox.SetSlaveAddress.Out.NewSlaveAddress,Local:1:O.Data[9],1) ,MOV(MVI69PDPMV1.Mailbox.SetSlaveAddress.Out.SlaveIdentNumber,Local:1:O.Data[10]) ,SWPB(MVI69PDPMV1.Mailbox.SetSlaveAddress.Out.No_add_Chg,REVERSE,MVI69PDPMV1.Util.ByteSwapUtil) ,MOV(MVI69PDPMV1.Util.ByteSwapUtil,Local:1:O.Data[11]) ,COP(MVI69PDPMV1.Mailbox.SetSlaveAddress.Out.MessageDataByte[0],Local:1:O.Data[17],42) ];
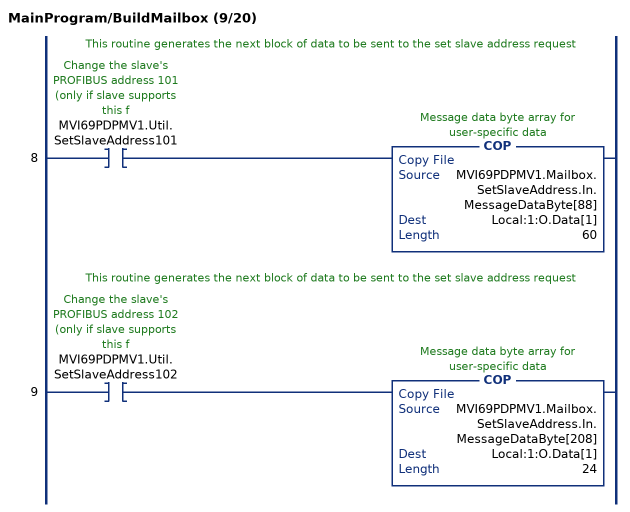
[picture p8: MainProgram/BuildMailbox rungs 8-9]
   // This routine generates the next block of data to be sent to the set slave address request
   8: XIC(MVI69PDPMV1.Util.SetSlaveAddress101)COP(MVI69PDPMV1.Mailbox.SetSlaveAddress.In.MessageDataByte[88],Local:1:O.Data[1],60);
   // This routine generates the next block of data to be sent to the set slave address request
   9: XIC(MVI69PDPMV1.Util.SetSlaveAddress102)COP(MVI69PDPMV1.Mailbox.SetSlaveAddress.In.MessageDataByte[208],Local:1:O.Data[1],24);
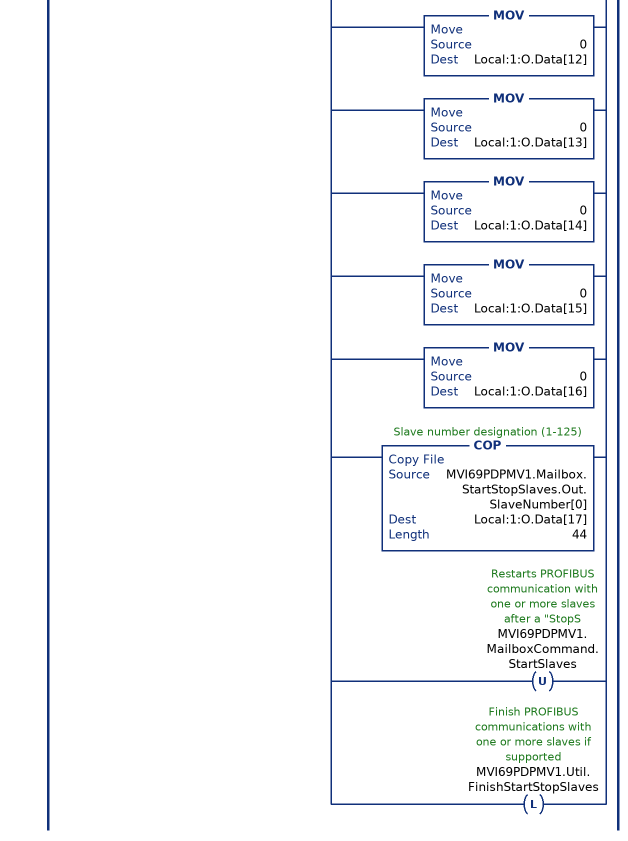
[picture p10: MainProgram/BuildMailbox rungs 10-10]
   // This routine generates the mailbox blocks according to the mailbox request (Set Slave Address)
   10: XIC(MVI69PDPMV1.MailboxCommand.StartSlaves)XIO(MVI69PDPMV1.Util.FinishStartStopSlaves)[MOV(16,Local:1:O.Data[1]) ,MOV(16386,Local:1:O.Data[2]) ,MOV(11,Local:1:O.Data[3]) ,MOV(126,Local:1:O.Data[4]) ,MOV(1,Local:1:O.Data[5]) ,MOV(1,Local:1:O.Data[6]) ,MOV(0,Local:1:O.Data[7]) ,MOV(0,Local:1:O.Data[8]) ,MOV(0,Local:1:O.Data[9]) ,MOV(0,Local:1:O.Data[10]) ,MOV(0,Local:1:O.Data[11]) ,MOV(0,Local:1:O.Data[12]) ,MOV(0,Local:1:O.Data[13]) ,MOV(0,Local:1:O.Data[14]) ,MOV(0,Local:1:O.Data[15]) ,MOV(0,Local:1:O.Data[16]) ,COP(MVI69PDPMV1.Mailbox.StartStopSlaves.Out.SlaveNumber[0],Local:1:O.Data[17],44) ,OTU(MVI69PDPMV1.MailboxCommand.StartSlaves) ,OTL(MVI69PDPMV1.Util.FinishStartStopSlaves) ];
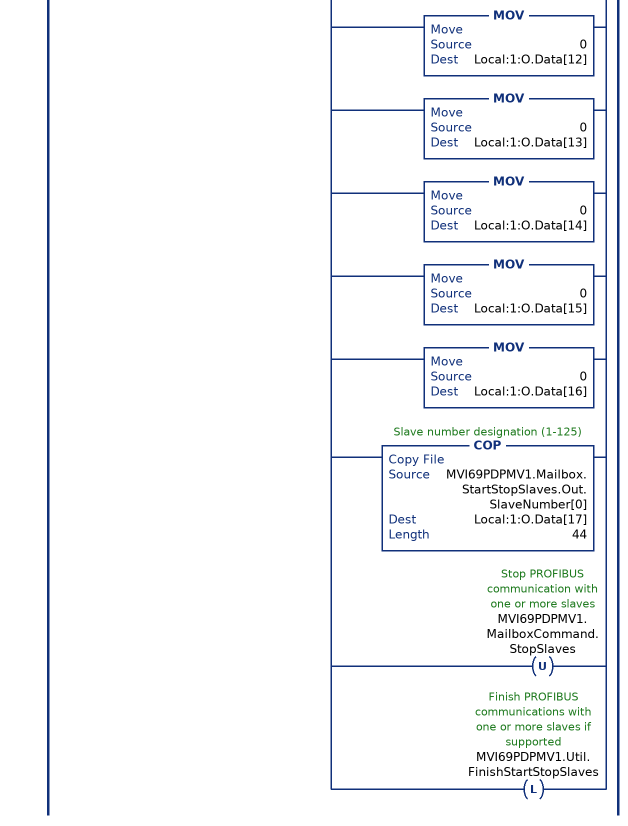
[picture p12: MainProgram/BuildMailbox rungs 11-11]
   // This routine generates the mailbox blocks according to the mailbox request (Set Slave Address)
   11: XIC(MVI69PDPMV1.MailboxCommand.StopSlaves)XIO(MVI69PDPMV1.Util.FinishStartStopSlaves)[MOV(17,Local:1:O.Data[1]) ,MOV(16386,Local:1:O.Data[2]) ,MOV(12,Local:1:O.Data[3]) ,MOV(126,Local:1:O.Data[4]) ,MOV(1,Local:1:O.Data[5]) ,MOV(1,Local:1:O.Data[6]) ,MOV(0,Local:1:O.Data[7]) ,MOV(0,Local:1:O.Data[8]) ,MOV(0,Local:1:O.Data[9]) ,MOV(0,Local:1:O.Data[10]) ,MOV(0,Local:1:O.Data[11]) ,MOV(0,Local:1:O.Data[12]) ,MOV(0,Local:1:O.Data[13]) ,MOV(0,Local:1:O.Data[14]) ,MOV(0,Local:1:O.Data[15]) ,MOV(0,Local:1:O.Data[16]) ,COP(MVI69PDPMV1.Mailbox.StartStopSlaves.Out.SlaveNumber[0],Local:1:O.Data[17],44) ,OTU(MVI69PDPMV1.MailboxCommand.StopSlaves) ,OTL(MVI69PDPMV1.Util.FinishStartStopSlaves) ];
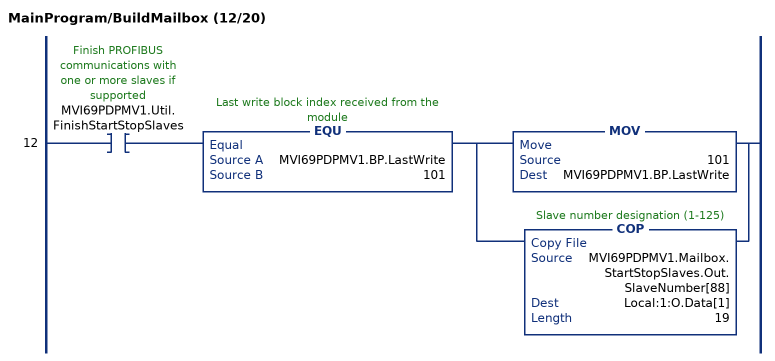
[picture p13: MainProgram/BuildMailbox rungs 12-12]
   12: XIC(MVI69PDPMV1.Util.FinishStartStopSlaves)EQU(MVI69PDPMV1.BP.LastWrite,101)[MOV(101,MVI69PDPMV1.BP.LastWrite) ,COP(MVI69PDPMV1.Mailbox.StartStopSlaves.Out.SlaveNumber[88],Local:1:O.Data[1],19) ];
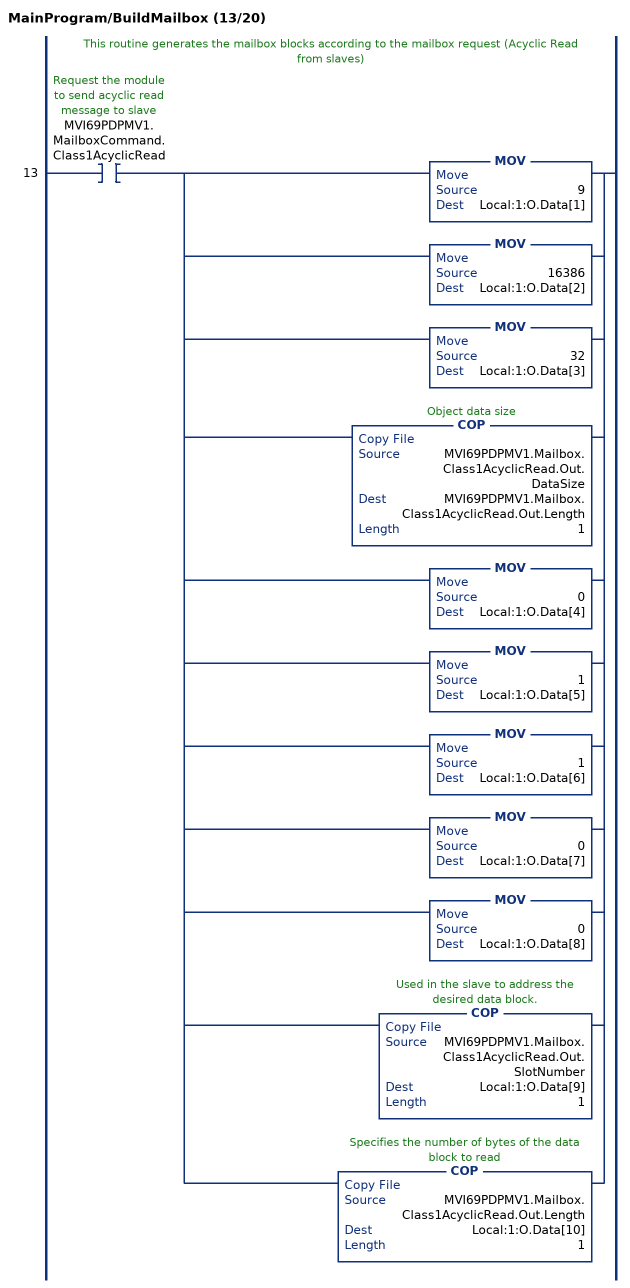
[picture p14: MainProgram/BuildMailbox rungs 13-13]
   // This routine generates the mailbox blocks according to the mailbox request (Acyclic Read from slaves)
   13: XIC(MVI69PDPMV1.MailboxCommand.Class1AcyclicRead)[MOV(9,Local:1:O.Data[1]) ,MOV(16386,Local:1:O.Data[2]) ,MOV(32,Local:1:O.Data[3]) ,COP(MVI69PDPMV1.Mailbox.Class1AcyclicRead.Out.DataSize,MVI69PDPMV1.Mailbox.Class1AcyclicRead.Out.Length,1) ,MOV(0,Local:1:O.Data[4]) ,MOV(1,Local:1:O.Data[5]) ,MOV(1,Local:1:O.Data[6]) ,MOV(0,Local:1:O.Data[7]) ,MOV(0,Local:1:O.Data[8]) ,COP(MVI69PDPMV1.Mailbox.Class1AcyclicRead.Out.SlotNumber,Local:1:O.Data[9],1) ,COP(MVI69PDPMV1.Mailbox.Class1AcyclicRead.Out.Length,Local:1:O.Data[10],1) ];
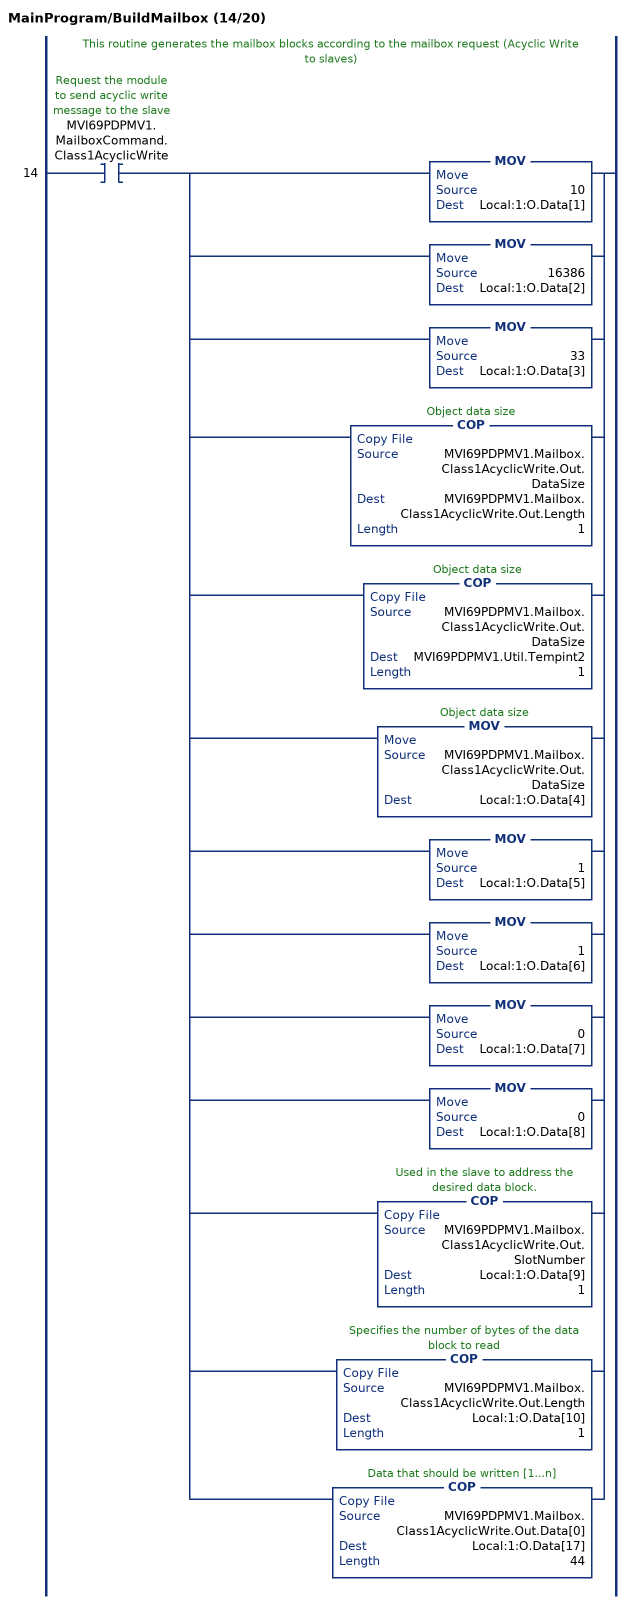
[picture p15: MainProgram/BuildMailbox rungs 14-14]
   // This routine generates the mailbox blocks according to the mailbox request (Acyclic Write to slaves)
   14: XIC(MVI69PDPMV1.MailboxCommand.Class1AcyclicWrite)[MOV(10,Local:1:O.Data[1]) ,MOV(16386,Local:1:O.Data[2]) ,MOV(33,Local:1:O.Data[3]) ,COP(MVI69PDPMV1.Mailbox.Class1AcyclicWrite.Out.DataSize,MVI69PDPMV1.Mailbox.Class1AcyclicWrite.Out.Length,1) ,COP(MVI69PDPMV1.Mailbox.Class1AcyclicWrite.Out.DataSize,MVI69PDPMV1.Util.Tempint2,1) ,MOV(MVI69PDPMV1.Mailbox.Class1AcyclicWrite.Out.DataSize,Local:1:O.Data[4]) ,MOV(1,Local:1:O.Data[5]) ,MOV(1,Local:1:O.Data[6]) ,MOV(0,Local:1:O.Data[7]) ,MOV(0,Local:1:O.Data[8]) ,COP(MVI69PDPMV1.Mailbox.Class1AcyclicWrite.Out.SlotNumber,Local:1:O.Data[9],1) ,COP(MVI69PDPMV1.Mailbox.Class1AcyclicWrite.Out.Length,Local:1:O.Data[10],1) ,COP(MVI69PDPMV1.Mailbox.Class1AcyclicWrite.Out.Data[0],Local:1:O.Data[17],44) ];
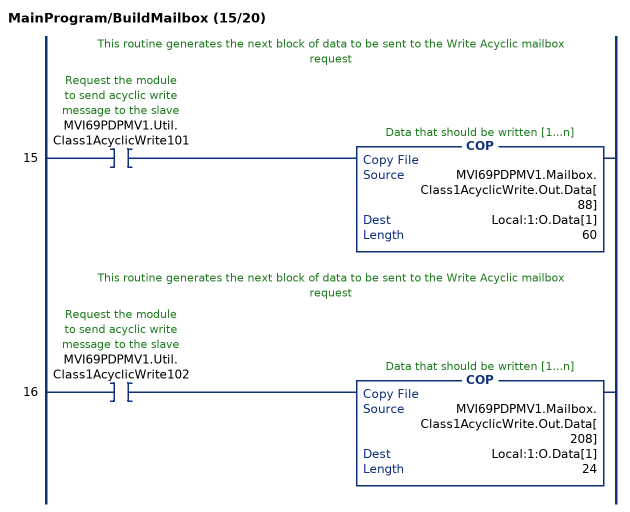
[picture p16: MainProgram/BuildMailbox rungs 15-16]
   // This routine generates the next block of data to be sent to the Write Acyclic mailbox request
   15: XIC(MVI69PDPMV1.Util.Class1AcyclicWrite101)COP(MVI69PDPMV1.Mailbox.Class1AcyclicWrite.Out.Data[88],Local:1:O.Data[1],60);
   // This routine generates the next block of data to be sent to the Write Acyclic mailbox request
   16: XIC(MVI69PDPMV1.Util.Class1AcyclicWrite102)COP(MVI69PDPMV1.Mailbox.Class1AcyclicWrite.Out.Data[208],Local:1:O.Data[1],24);
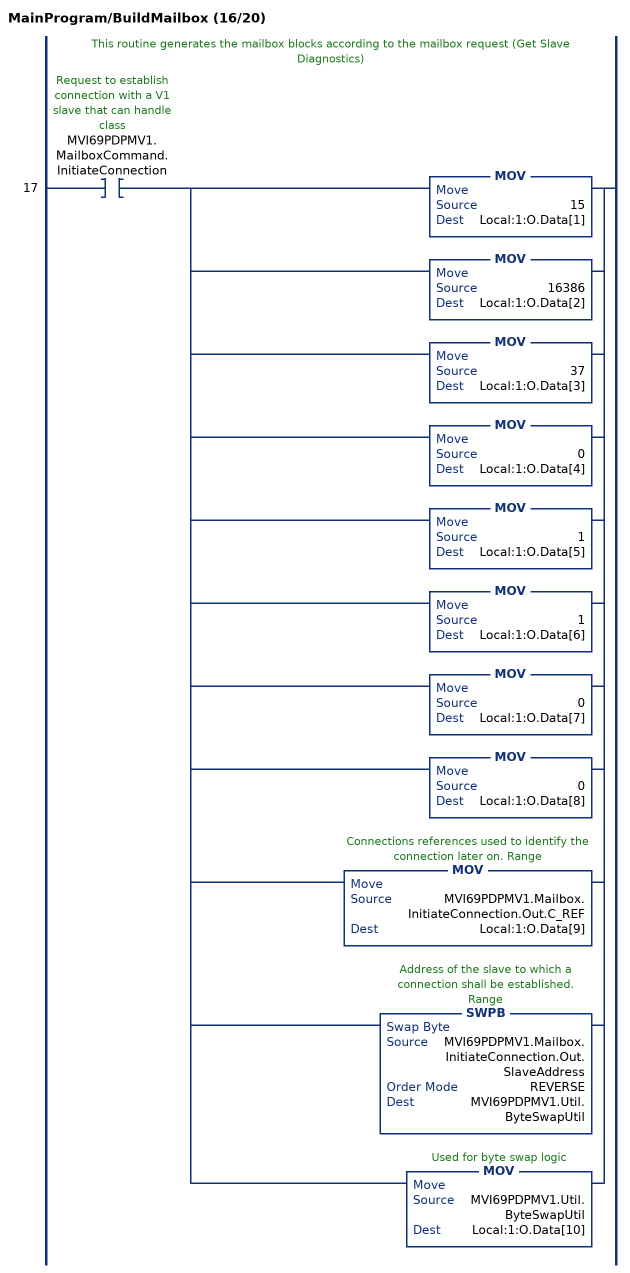
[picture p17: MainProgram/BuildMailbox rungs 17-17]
   // This routine generates the mailbox blocks according to the mailbox request (Get Slave Diagnostics)
   17: XIC(MVI69PDPMV1.MailboxCommand.InitiateConnection)[MOV(15,Local:1:O.Data[1]) ,MOV(16386,Local:1:O.Data[2]) ,MOV(37,Local:1:O.Data[3]) ,MOV(0,Local:1:O.Data[4]) ,MOV(1,Local:1:O.Data[5]) ,MOV(1,Local:1:O.Data[6]) ,MOV(0,Local:1:O.Data[7]) ,MOV(0,Local:1:O.Data[8]) ,MOV(MVI69PDPMV1.Mailbox.InitiateConnection.Out.C_REF,Local:1:O.Data[9]) ,SWPB(MVI69PDPMV1.Mailbox.InitiateConnection.Out.SlaveAddress,REVERSE,MVI69PDPMV1.Util.ByteSwapUtil) ,MOV(MVI69PDPMV1.Util.ByteSwapUtil,Local:1:O.Data[10]) ];
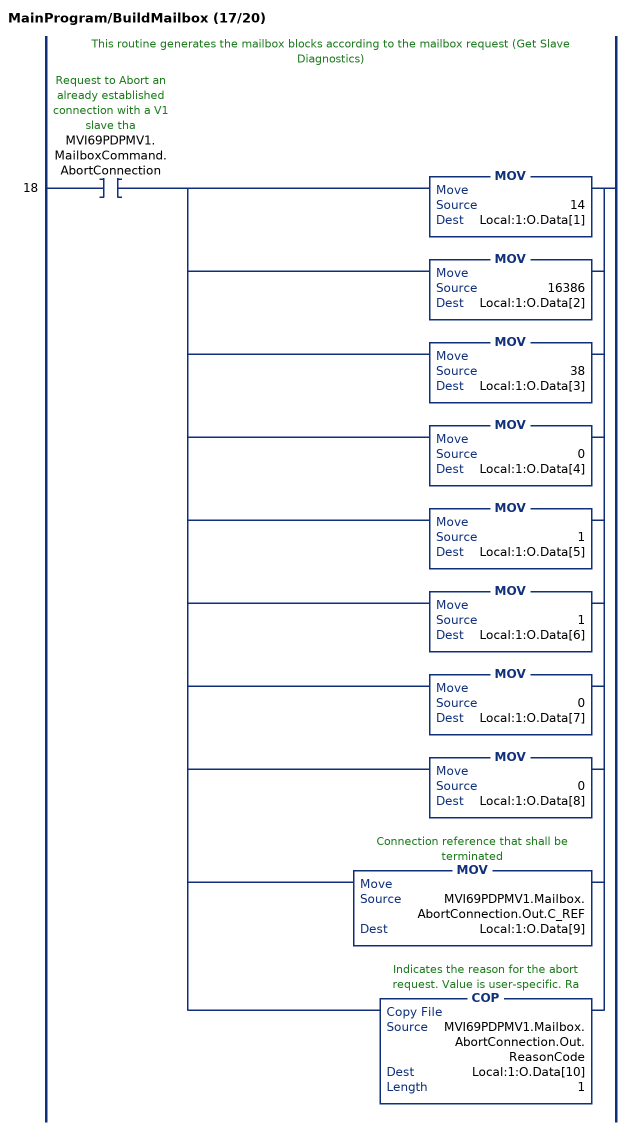
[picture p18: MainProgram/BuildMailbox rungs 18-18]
   // This routine generates the mailbox blocks according to the mailbox request (Get Slave Diagnostics)
   18: XIC(MVI69PDPMV1.MailboxCommand.AbortConnection)[MOV(14,Local:1:O.Data[1]) ,MOV(16386,Local:1:O.Data[2]) ,MOV(38,Local:1:O.Data[3]) ,MOV(0,Local:1:O.Data[4]) ,MOV(1,Local:1:O.Data[5]) ,MOV(1,Local:1:O.Data[6]) ,MOV(0,Local:1:O.Data[7]) ,MOV(0,Local:1:O.Data[8]) ,MOV(MVI69PDPMV1.Mailbox.AbortConnection.Out.C_REF,Local:1:O.Data[9]) ,COP(MVI69PDPMV1.Mailbox.AbortConnection.Out.ReasonCode,Local:1:O.Data[10],1) ];
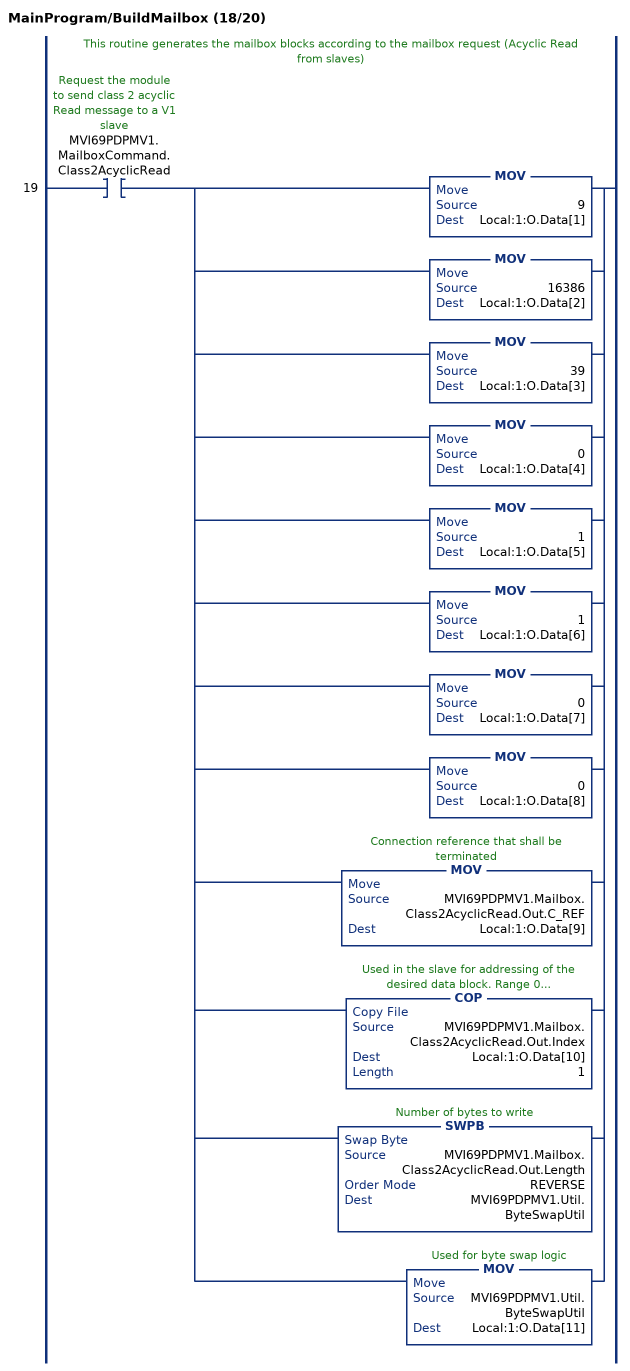
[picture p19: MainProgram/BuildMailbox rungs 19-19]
   // This routine generates the mailbox blocks according to the mailbox request (Acyclic Read from slaves)
   19: XIC(MVI69PDPMV1.MailboxCommand.Class2AcyclicRead)[MOV(9,Local:1:O.Data[1]) ,MOV(16386,Local:1:O.Data[2]) ,MOV(39,Local:1:O.Data[3]) ,MOV(0,Local:1:O.Data[4]) ,MOV(1,Local:1:O.Data[5]) ,MOV(1,Local:1:O.Data[6]) ,MOV(0,Local:1:O.Data[7]) ,MOV(0,Local:1:O.Data[8]) ,MOV(MVI69PDPMV1.Mailbox.Class2AcyclicRead.Out.C_REF,Local:1:O.Data[9]) ,COP(MVI69PDPMV1.Mailbox.Class2AcyclicRead.Out.Index,Local:1:O.Data[10],1) ,SWPB(MVI69PDPMV1.Mailbox.Class2AcyclicRead.Out.Length,REVERSE,MVI69PDPMV1.Util.ByteSwapUtil) ,MOV(MVI69PDPMV1.Util.ByteSwapUtil,Local:1:O.Data[11]) ];
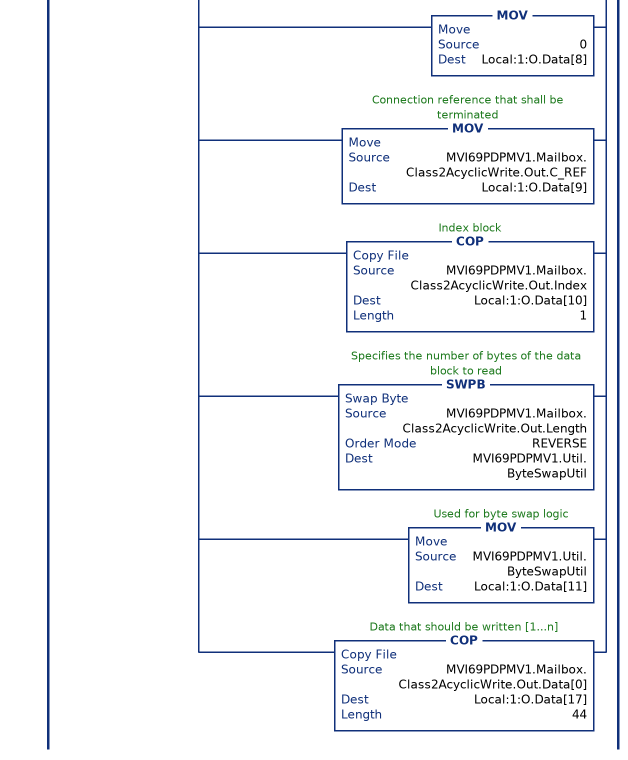
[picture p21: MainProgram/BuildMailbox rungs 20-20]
   // This routine generates the mailbox blocks according to the mailbox request (Acyclic Write to slaves)
   20: XIC(MVI69PDPMV1.MailboxCommand.Class2AcyclicWrite)[MOV(10,Local:1:O.Data[1]) ,MOV(16386,Local:1:O.Data[2]) ,MOV(40,Local:1:O.Data[3]) ,COP(MVI69PDPMV1.Mailbox.Class2AcyclicWrite.Out.DataSize,MVI69PDPMV1.Mailbox.Class2AcyclicWrite.Out.Length,1) ,COP(MVI69PDPMV1.Mailbox.Class2AcyclicWrite.Out.DataSize,MVI69PDPMV1.Util.Tempint2,1) ,MOV(MVI69PDPMV1.Mailbox.Class2AcyclicWrite.Out.DataSize,Local:1:O.Data[4]) ,MOV(1,Local:1:O.Data[5]) ,MOV(1,Local:1:O.Data[6]) ,MOV(0,Local:1:O.Data[7]) ,MOV(0,Local:1:O.Data[8]) ,MOV(MVI69PDPMV1.Mailbox.Class2AcyclicWrite.Out.C_REF,Local:1:O.Data[9]) ,COP(MVI69PDPMV1.Mailbox.Class2AcyclicWrite.Out.Index,Local:1:O.Data[10],1) ,SWPB(MVI69PDPMV1.Mailbox.Class2AcyclicWrite.Out.Length,REVERSE,MVI69PDPMV1.Util.ByteSwapUtil) ,MOV(MVI69PDPMV1.Util.ByteSwapUtil,Local:1:O.Data[11]) ,COP(MVI69PDPMV1.Mailbox.Class2AcyclicWrite.Out.Data[0],Local:1:O.Data[17],44) ];
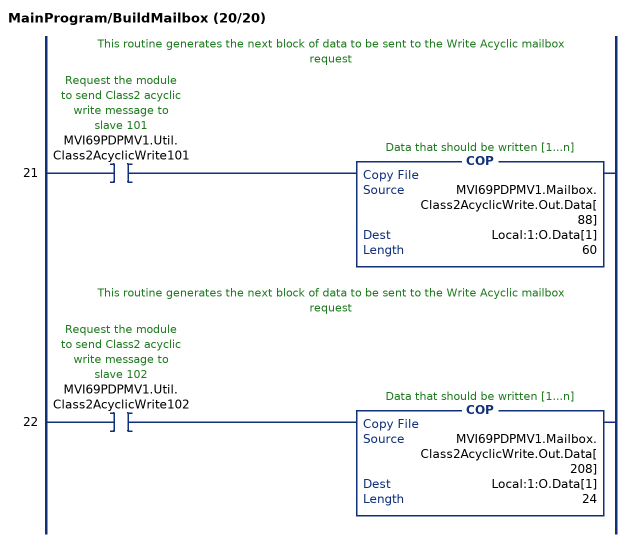
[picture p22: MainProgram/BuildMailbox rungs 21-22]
   // This routine generates the next block of data to be sent to the Write Acyclic mailbox request
   21: XIC(MVI69PDPMV1.Util.Class2AcyclicWrite101)COP(MVI69PDPMV1.Mailbox.Class2AcyclicWrite.Out.Data[88],Local:1:O.Data[1],60);
   // This routine generates the next block of data to be sent to the Write Acyclic mailbox request
   22: XIC(MVI69PDPMV1.Util.Class2AcyclicWrite102)COP(MVI69PDPMV1.Mailbox.Class2AcyclicWrite.Out.Data[208],Local:1:O.Data[1],24);
END_ROUTINE
